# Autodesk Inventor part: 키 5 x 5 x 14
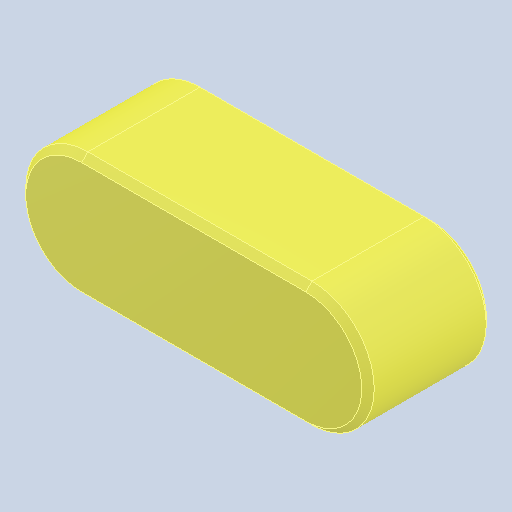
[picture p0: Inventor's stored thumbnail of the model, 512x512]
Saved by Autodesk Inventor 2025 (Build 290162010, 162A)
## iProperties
Created: 2024-07
Part Number: 키 5 x 5 x 14
Material: 강철, 연강
Description: 키 및 해당 키홈
Document SubType Name: Modeling
Designer: 계정
Density: 7.85 g/cm^3
Appearance: 기본값
Author: jhkim
Sending System: Autodesk Inventor 2025
Preprocessor: ST-DEVELOPER v20
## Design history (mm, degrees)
feature "Solid1"
node "솔리드1"
